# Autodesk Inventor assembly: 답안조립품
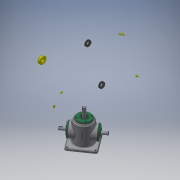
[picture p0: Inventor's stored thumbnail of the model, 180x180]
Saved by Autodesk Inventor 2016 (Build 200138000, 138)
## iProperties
Created: 2019-08
Part Number: 답안조립품
Material: 일반
Document SubType Name: Assembly
Designer: user
Author: user
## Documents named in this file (14)
- D:\490823V1001\답안조립품.iam
- D:\490823V1001\본체.ipj.ipt
- D:\490823V1001\메인 베벨기어.ipt
- D:\490823V1001\메인 축.ipt
- 메인 축.ipt
- D:\490823V1001\베어링 6203.ipt
- D:\490823V1001\볼트 M4.ipt
- 볼트 M4.ipt
- D:\490823V1001\서브 베벨기어.ipt
- D:\490823V1001\오일 실.ipt
- 오일 실.ipt
- D:\490823V1001\커버.ipt
- D:\490823V1001\키 4x4.ipt
- D:\490823V1001\키 5x5.ipt
